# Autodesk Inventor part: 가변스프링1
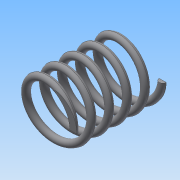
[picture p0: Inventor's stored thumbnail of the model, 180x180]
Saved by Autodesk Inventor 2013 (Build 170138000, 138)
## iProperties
Created: 2018-10
Part Number: 가변스프링1
Material: 일반
Document SubType Name: Modeling
Designer: Administrator
Density: 1 g/cm^3
Mass: 0.777104 g
Surface Area: 15.7644 cm^2
Volume: 0.777104 cm^3
Author: Administrator
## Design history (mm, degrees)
sketch "스케치1"
  geometry: L1 (0, 0)-(8, 0); L2 (0, 0)-(0, 25.52); L3 (0, 25.52)-(8, 25.52); C1 r 1 at (8, 0)
  constraints: 6 end point, 2 perpendicular, 1 centre point, 1 coincident, 1 horizontal
  dimensions: "d0" = 8 distance of L1.start L1.end; "d1" = 25.5198 distance of L1.start L2.end (derived); "d2" = 8 distance of L2.end L3.end; "d3" = 2 diameter of C1
feature "코일1" sketch "스케치1" pitch "d4" = 10; turns "d6" = 5; dims "d5" = 25.5198 (= d1), "d7" = 0, angle "d8" = 90 deg, angle "d9" = 90 deg, "d10" = 0, "d11" = 0
sketch "스케치2"
  geometry: L1 (25.52, 9.5)-(0, 9.5); L2 (0, 9.5)-(0, -9.5); L3 (0, -9.5)-(25.52, -9.5); L4 (25.52, -9.5)-(25.52, 9.5); 2 further points
  constraints: 8 end point, 2 parallel, 1 coincident, 1 horizontal, 1 midpoint, 1 perpendicular
  dimensions: "d12" = 25.5198 distance from line of point (0, 0) L4 (derived); "d13" = 19 distance between parallel lines of L3 L1
extrude "돌출1" sketch "스케치2" stored distance "d14" = 0; taper "d15" = 0 deg
node "솔리드1"
